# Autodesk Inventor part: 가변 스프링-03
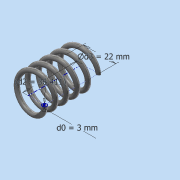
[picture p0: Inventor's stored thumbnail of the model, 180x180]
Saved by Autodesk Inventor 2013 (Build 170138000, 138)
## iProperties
Created: 2014-12
Part Number: 가변 스프링-03
Material: 강철, 탄소
Document SubType Name: Modeling
Designer: WINDOWS7
Density: 7.87 g/cm^3
Mass: 18.8927 g
Surface Area: 32.5299 cm^2
Volume: 2.40059 cm^3
Author: WINDOWS7
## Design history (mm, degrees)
sketch "스케치1"
  geometry: L1 (0, 0)-(11, 0); L2 (11, 0)-(11, 36.411); L3 (11, 36.411)-(0, 36.411); L4 (0, 36.411)-(0, 0); C1 r 1.5 at (11, 0)
  constraints: 8 end point, 2 parallel, 1 centre point, 1 coincident, 1 horizontal, 1 perpendicular
  dimensions: "d0" = 3 diameter of C1; "d2" = 36.4112 distance of L3.end L1.start (derived); "d3" = 22 diameter of L2 L4
feature "코일1" pitch "d4" = 10; turns "d6" = 5; dims "d5" = 36.4112 (= d2), "d7" = 0, angle "d8" = 90 deg, angle "d9" = 90 deg, "d10" = 0, "d11" = 0
node "작업 평면1"
sketch "스케치2"
  geometry: L1 (-12.5, 0)-(-9.5, 0) reference; 1 further point
  constraints: 1 horizontal alignment
extrude "돌출1" cut sketch "스케치2" distance "d13" = 10; taper "d14" = 0 deg
node "작업 평면2"
sketch "스케치3"
  geometry: L1 (-9.5, 0)-(-12.5, 0) reference; 1 further point
  constraints: 1 horizontal alignment
extrude "돌출2" cut sketch "스케치3" distance "d16" = 10; taper "d17" = 0 deg
node "솔리드1"
node "절단 모서리 투영1"
node "절단 모서리 투영2"
other parameters: "d12" = 0, "d15" = 36.4112 (= d2)
